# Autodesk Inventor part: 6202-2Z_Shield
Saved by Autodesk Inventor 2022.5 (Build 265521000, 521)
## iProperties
Created: 2024-12
Part Number: 6202-2Z_Shield
Material: Generic
Document SubType Name: Modeling
Designer: AdminForWorker
Density: 1 g/cm^3
Appearance: Default
Title: 6202-2Z_Shield
Author: AdminForWorker
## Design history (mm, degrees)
feature "Body1"
body "Solid1"
